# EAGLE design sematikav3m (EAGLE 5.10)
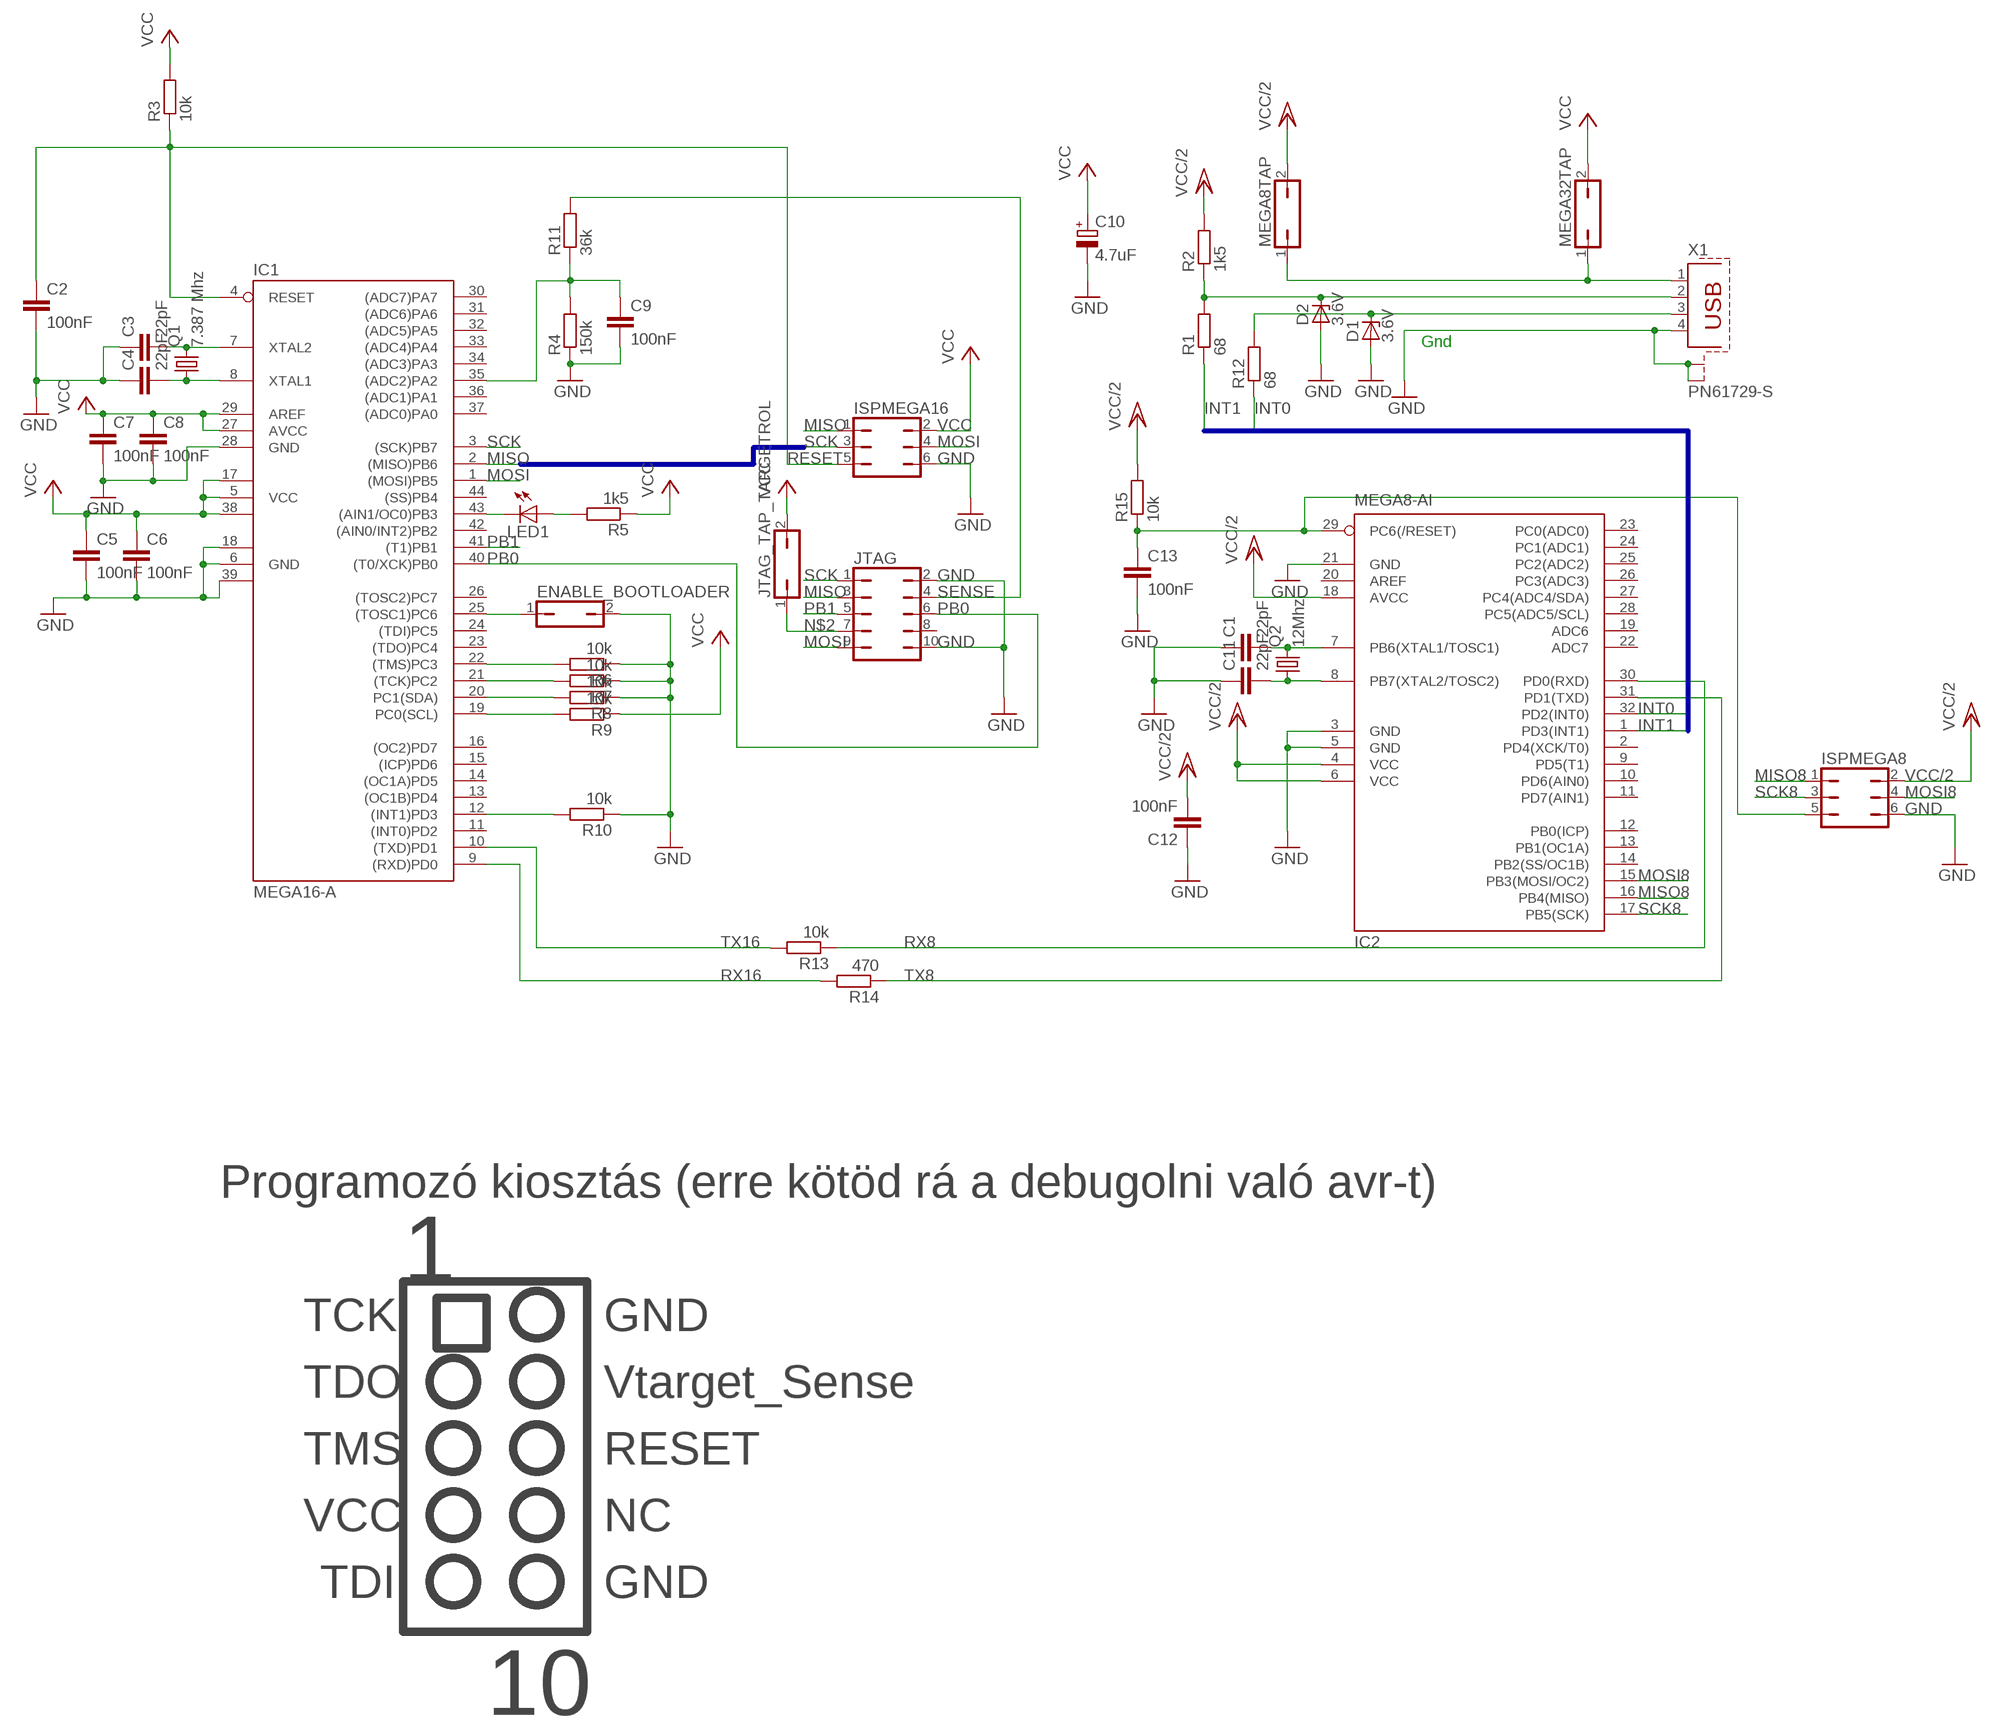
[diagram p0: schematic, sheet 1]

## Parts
C1  22pF  C-EUC1206  [C1206]
C2  100nF  C-EUC1206  [C1206]
C3  22pF  C-EUC1206  [C1206]
C4  22pF  C-EUC1206  [C1206]
C5  100nF  C-EUC1206  [C1206]
C6  100nF  C-EUC1206  [C1206]
C7  100nF  C-EUC1206  [C1206]
C8  100nF  C-EUC1206  [C1206]
C9  100nF  C-EUC1206  [C1206]
C10  4.7uF  CPOL-EUE2,5-6E  [E2,5-6E]
C11  22pF  C-EUC1206  [C1206]
C12  100nF  C-EUC1206  [C1206]
C13  100nF  C-EUC1206  [C1206]
D1  3.6V  ZENER-DIODEDO35Z10  [DO35Z10]
D2  3.6V  ZENER-DIODEDO35Z10  [DO35Z10]
ENABLE_BOOTLOADER  JP1Q  [JP1]
IC1  MEGA16-A  [TQFP44]
IC2  MEGA8-AI  [TQFP32-08]
ISPMEGA8  JP3Q  [JP3Q]
ISPMEGA16  JP3Q  [JP3Q]
JTAG  JP5Q  [JP5Q]
JTAG_TAP_TARGETROL  JP1Q  [JP1]
LED1  LED3MM  [LED3MM]
MEGA8TAP  JP1Q  [JP1]
MEGA32TAP  JP1Q  [JP1]
Q1  7.387 Mhz  CRYSTALHC49U-V  [HC49U-V]
Q2  12Mhz  CRYSTALHC49U-V  [HC49U-V]
R1  68  R-EU_R1206  [R1206]
R2  1k5  R-EU_R1206  [R1206]
R3  10k  R-EU_R1206  [R1206]
R4  150k  R-EU_R1206  [R1206]
R5  1k5  R-EU_R1206  [R1206]
R6  10k  R-EU_R1206  [R1206]
R7  10k  R-EU_R1206  [R1206]
R8  10k  R-EU_R1206  [R1206]
R9  10k  R-EU_R1206  [R1206]
R10  10k  R-EU_R1206  [R1206]
R11  36k  R-EU_R1206  [R1206]
R12  68  R-EU_R1206  [R1206]
R13  10k  R-EU_R1206  [R1206]
R14  470  R-EU_R1206  [R1206]
R15  10k  R-EU_R1206  [R1206]
X1  PN61729-S  [PN61729-S]

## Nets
D+: D1.C R12.2 X1.3
D-: D2.C R1.2 R2.1 X1.2
GND: C1.1 C2.2 C3.1 C4.1 C5.2 C6.2 C7.2 C8.2 C9.2 C10.- C11.1 C12.1 C13.2 D1.A D2.A ENABLE_BOOTLOADER.2 IC1.6(GND) IC1.18(GND1) IC1.28(GND) IC1.39(GND2) IC2.3(GND) IC2.5(GND) IC2.21(GND) ISPMEGA8.6 ISPMEGA16.6 JTAG.2 JTAG.10 R4.1 R6.1 R7.1 R8.1 R10.1 X1.4 X1.S1 X1.S2
INT0: IC2.32(PD2(INT0)) R12.1
INT1: IC2.1(PD3(INT1)) R1.1
MISO: IC1.2((MISO)PB6) ISPMEGA16.1 JTAG.3
MISO8: IC2.16(PB4(MISO)) ISPMEGA8.1
MOSI: IC1.1((MOSI)PB5) ISPMEGA16.4 JTAG.9
MOSI8: IC2.15(PB3(MOSI/OC2)) ISPMEGA8.4
N$2: JTAG.7 JTAG_TAP_TARGETROL.1
N$6: C11.2 IC2.8(PB7(XTAL2/TOSC2)) Q2.1
N$7: C1.2 IC2.7(PB6(XTAL1/TOSC1)) Q2.2
N$9: IC1.22((TMS)PC3) R6.2
N$10: C3.2 IC1.7(XTAL2) Q1.2
N$11: C4.2 IC1.8(XTAL1) Q1.1
N$12: C9.1 IC1.35((ADC2)PA2) R4.2 R11.1
N$13: IC1.21((TCK)PC2) R7.2
N$14: IC1.43((AIN1/OC0)PB3) LED1.K(C)
N$15: LED1.A R5.2
N$16: ENABLE_BOOTLOADER.1 IC1.25((TOSC1)PC6)
N$17: IC1.20(PC1(SDA)) R8.2
N$18: IC1.19(PC0(SCL)) R9.2
N$19: IC1.12((INT1)PD3) R10.2
N$23: MEGA8TAP.1 MEGA32TAP.1 X1.1
PB0: IC1.40((T0/XCK)PB0) JTAG.6
PB1: IC1.41((T1)PB1) JTAG.5
RESET: C2.1 IC1.4(RESET) ISPMEGA16.5 R3.1
RESET8: C13.1 IC2.29(PC6(/RESET)) ISPMEGA8.5 R15.1
RX8: IC2.30(PD0(RXD)) R13.1
RX16: IC1.9((RXD)PD0) R14.2
SCK: IC1.3((SCK)PB7) ISPMEGA16.3 JTAG.1
SCK8: IC2.17(PB5(SCK)) ISPMEGA8.3
SENSE: JTAG.4 R11.2
TX8: IC2.31(PD1(TXD)) R14.1
TX16: IC1.10((TXD)PD1) R13.2
VCC: C5.1 C6.1 C7.1 C8.1 C10.+ IC1.5(VCC) IC1.17(VCC1) IC1.27(AVCC) IC1.29(AREF) IC1.38(VCC2) ISPMEGA16.2 JTAG_TAP_TARGETROL.2 MEGA32TAP.2 R3.2 R5.1 R9.1
VCC/2: C12.2 IC2.4(VCC) IC2.6(VCC) IC2.18(AVCC) ISPMEGA8.2 MEGA8TAP.2 R2.2 R15.2
Unconnected: IC1.11((INT0)PD2) IC1.13((OC1B)PD4) IC1.14((OC1A)PD5) IC1.15((ICP)PD6) IC1.16((OC2)PD7) IC1.23((TDO)PC4) IC1.24((TDI)PC5) IC1.26((TOSC2)PC7) IC1.30((ADC7)PA7) IC1.31((ADC6)PA6) IC1.32((ADC5)PA5) IC1.33((ADC4)PA4) IC1.34((ADC3)PA3) IC1.36((ADC1)PA1) IC1.37((ADC0)PA0) IC1.42((AIN0/INT2)PB2) IC1.44((SS)PB4) IC2.2(PD4(XCK/T0)) IC2.9(PD5(T1)) IC2.10(PD6(AIN0)) IC2.11(PD7(AIN1)) IC2.12(PB0(ICP)) IC2.13(PB1(OC1A)) IC2.14(PB2(SS/OC1B)) IC2.19(ADC6) IC2.20(AREF) IC2.22(ADC7) IC2.23(PC0(ADC0)) IC2.24(PC1(ADC1)) IC2.25(PC2(ADC2)) IC2.26(PC3(ADC3)) IC2.27(PC4(ADC4/SDA)) IC2.28(PC5(ADC5/SCL)) JTAG.8

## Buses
B$1
B$2

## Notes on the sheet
- Gnd
- Programozó kiosztás (erre kötöd rá a debugolni való avr-t)
- 1
- TCK | GND
- TDO | Vtarget_Sense
- TMS | RESET
- VCC | NC
- TDI | GND
- 10

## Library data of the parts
C1-C9 C11-C13 = rcl:C-EU: CAPACITOR, European symbol
C10 = rcl:CPOL-EU: POLARIZED CAPACITOR, European symbol
D1 D2 = diode:ZENER-DIODE: Z-Diode
ENABLE_BOOTLOADER JTAG_TAP_TARGETROL MEGA8TAP MEGA32TAP = jumper:JP1Q: JUMPER
IC1 = atmel:MEGA16: MICROCONTROLLER 16 Kbytes FLASH 1 kbytes SRAM 512 bytes EEPROM USART 8-channel 10 bit ADC Source: avr.lbr
IC2 = atmel:MEGA8: MICROCONTROLLER 8 Kbytes FLASH, 1 kbytes SRAM, 512 bytes EEPROM, USART, 6-channel 10 bit ADC, 2-channel 8 bit ADC Pin compatible with Atmega48, ATMega88, ATMega168 Source: avr.lbr
ISPMEGA8 ISPMEGA16 = jumper:JP3Q: JUMPER
JTAG = jumper:JP5Q: JUMPER
LED1 = led:LED: LED
Q1 Q2 = crystal:CRYSTAL: CRYSTAL
R1-R15 = resistor:R-EU_: RESISTOR, European symbol
X1 = con-berg:PN61729-S: BERG USB connector

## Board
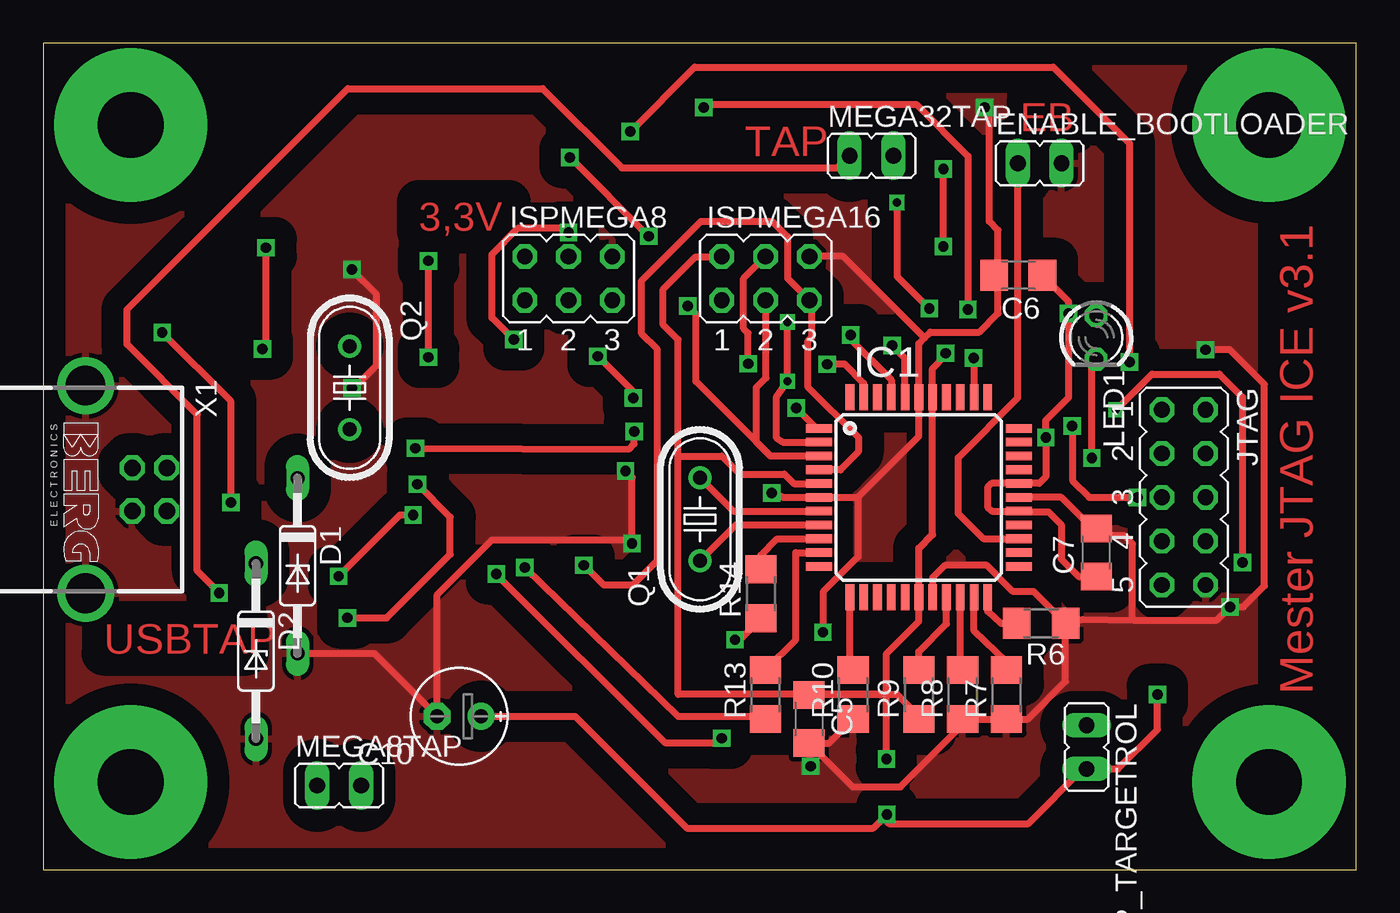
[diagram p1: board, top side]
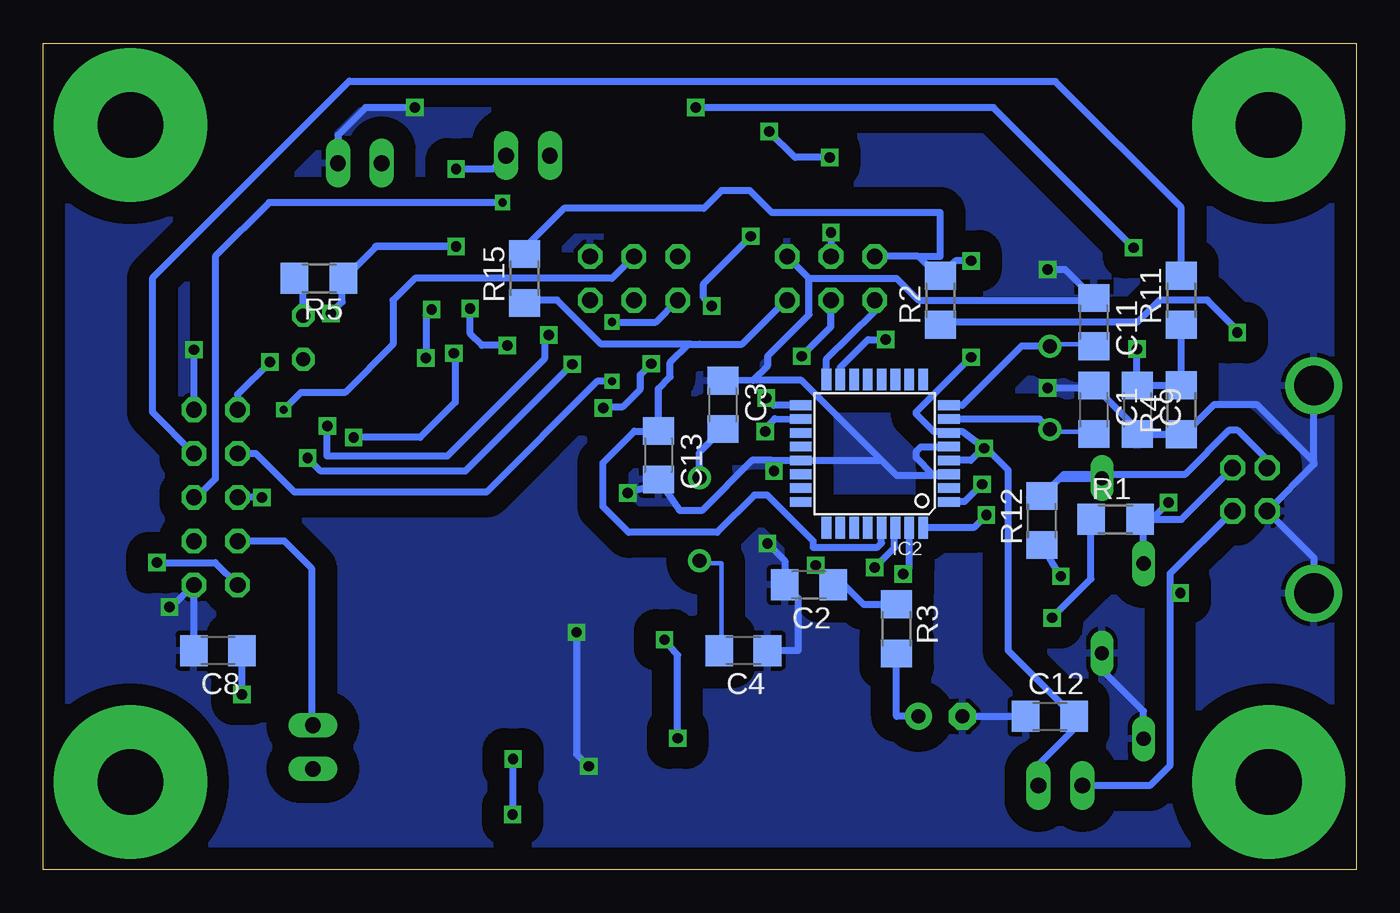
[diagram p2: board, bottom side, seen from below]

Size 76.18 x 47.93 mm. Coordinates in mm from the lower left corner, seen from the top.
Outline: 0,0 76.18,0 76.18,47.93 0,47.93 0,0
Copper layers (1*16): Top 0.035mm / dielectric 1.5mm / Bottom 0.035mm
Design rules "default *": minimum track width 10mil, minimum drill 19mil, track to track 8mil, track to pad 8mil, pad to pad 8mil, via to via 8mil, smd to smd 8mil, copper to edge 40mil, drill to drill 8mil, minimum pad ring 10mil, minimum via ring 8mil, stop-mask expansion 4mil, vias tented up to drill 0mil, thermal gap 10mil

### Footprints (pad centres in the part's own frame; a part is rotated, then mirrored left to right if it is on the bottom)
C1206 = smd 1.6 x 1.8: 1 -1.4,0; 2 1.4,0
E2,5-6E = drill 0.813 pad 1.575 round: + -1.27,0 | drill 0.813 pad 1.575 octagon: - 1.27,0
DO35Z10 = drill 0.813 long: A 5.08,0; C -5.08,0
JP1 = drill 0.914 long: 1 0,-1.27; 2 0,1.27
TQFP44 = smd 1.5 x 0.5: 1 -5.8,4; 2 -5.8,3.2; 3 -5.8,2.4; 4 -5.8,1.6; 5 -5.8,0.8; 6 -5.8,0; 7 -5.8,-0.8; 8 -5.8,-1.6; 9 -5.8,-2.4; 10 -5.8,-3.2; 11 -5.8,-4; 23 5.8,-4; 24 5.8,-3.2; 25 5.8,-2.4; 26 5.8,-1.6; 27 5.8,-0.8; 28 5.8,0; 29 5.8,0.8; 30 5.8,1.6; 31 5.8,2.4; 32 5.8,3.2; 33 5.8,4 | smd 0.5 x 1.5: 12 -4,-5.8; 13 -3.2,-5.8; 14 -2.4,-5.8; 15 -1.6,-5.8; 16 -0.8,-5.8; 17 0,-5.8; 18 0.8,-5.8; 19 1.6,-5.8; 20 2.4,-5.8; 21 3.2,-5.8; 22 4,-5.8; 34 4,5.8; 35 3.2,5.8; 36 2.4,5.8; 37 1.6,5.8; 38 0.8,5.8; 39 0,5.8; 40 -0.8,5.8; 41 -1.6,5.8; 42 -2.4,5.8; 43 -3.2,5.8; 44 -4,5.8
TQFP32-08 = smd 1.27 x 0.559: 1 -4.293,2.8; 2 -4.293,2; 3 -4.293,1.2; 4 -4.293,0.4; 5 -4.293,-0.4; 6 -4.293,-1.2; 7 -4.293,-2; 8 -4.293,-2.8; 17 4.293,-2.8; 18 4.293,-2; 19 4.293,-1.2; 20 4.293,-0.4; 21 4.293,0.4; 22 4.293,1.2; 23 4.293,2; 24 4.293,2.8 | smd 0.559 x 1.27: 9 -2.8,-4.293; 10 -2,-4.293; 11 -1.2,-4.293; 12 -0.4,-4.293; 13 0.4,-4.293; 14 1.2,-4.293; 15 2,-4.293; 16 2.8,-4.293; 25 2.8,4.293; 26 2,4.293; 27 1.2,4.293; 28 0.4,4.293; 29 -0.4,4.293; 30 -1.2,4.293; 31 -2,4.293; 32 -2.8,4.293
JP3Q = drill 0.914 octagon: 1 -2.54,-1.27; 2 -2.54,1.27; 3 0,-1.27; 4 0,1.27; 5 2.54,-1.27; 6 2.54,1.27
JP5Q = drill 0.914 octagon: 1 -5.08,-1.27; 2 -5.08,1.27; 3 -2.54,-1.27; 4 -2.54,1.27; 5 0,-1.27; 6 0,1.27; 7 2.54,-1.27; 8 2.54,1.27; 9 5.08,-1.27; 10 5.08,1.27
LED3MM = drill 0.813 octagon: A -1.27,0; K 1.27,0
HC49U-V = drill 0.813 round: 1 -2.413,0; 2 2.413,0
R1206 = smd 1.6 x 1.803: 1 -1.422,0; 2 1.422,0
PN61729-S = drill 0.95 octagon: 1 1.25,4.71; 2 -1.25,4.71; 3 -1.25,2.71; 4 1.25,2.71 | drill 2.3 pad 2.9 round: S1 -6.02,0; S2 6.02,0

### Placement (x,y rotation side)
C1  15.24,26.67 270 bottom
C2  31.75,16.51 180 bottom
C3  36.75,26.95 270 bottom
C4  35.56,12.7 180 bottom
C5  44.42,8.74 270 top
C6  56.57,34.47 180 top
C7  61.09,18.39 90 top
C8  66.04,12.7 180 bottom
C9  12.7,26.67 270 bottom
C10  24.13,8.89 180 top
C11  15.24,31.75 270 bottom
C12  17.78,8.89 0 bottom
C13  40.49,24.03 270 bottom
D1  14.76,17.63 270 top
D2  12.34,12.67 270 top
ENABLE_BOOTLOADER  57.81,40.97 270 top
IC1  50.8,21.59 0 top
IC2  27.94,24.13 180 bottom
ISPMEGA8  30.48,34.29 0 top
ISPMEGA16  41.91,34.29 0 top
JTAG  66.17,21.59 270 top
JTAG_TAP_TARGETROL  60.53,7.11 180 top
LED1  61.09,30.86 270 top
MEGA8TAP  17.17,4.88 270 top
MEGA32TAP  48.06,41.4 270 top
Q1  38.1,20.32 90 top
Q2  17.78,27.94 270 top
R1  13.97,20.32 0 bottom
R2  24.13,33.02 90 bottom
R3  26.67,13.97 270 bottom
R4  10.16,26.67 90 bottom
R5  60.17,34.29 180 bottom
R6  57.89,14.29 180 top
R7  55.88,10.16 90 top
R8  53.34,10.16 90 top
R9  50.8,10.16 90 top
R10  46.99,10.16 90 top
R11  10.16,33.02 90 bottom
R12  18.24,20.24 90 bottom
R13  41.91,10.16 90 top
R14  41.63,16 90 top
R15  48.26,34.29 90 bottom
X1  2.46,22.05 270 top

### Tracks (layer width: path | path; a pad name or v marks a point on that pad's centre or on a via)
D+
  Bottom 0.254: R12.2 19.05,21.59
  Bottom 0.406: X1.3 5.17,23.77 6.88,25.48 7.39,25.48 9.96,22.91 16.99,22.91 R12.2 17.2,22.71 D1.C
D-  (via drill 0.6)
  Top 0.406: v6.91,31.14 10.9,27.15 v10.9,21.29
  Bottom 0.254: R1.2 12.7,20.32 | 24.13,31.75 R2.1
  Bottom 0.406: 24.13,31.75 12.7,31.75 11.43,33.02 8.64,33.02 6.91,31.29 v6.91,31.14 | 11.86,20.32 10.15,20.32 X1.2 | 11.86,20.32 v10.9,21.29 | 11.86,20.32 R1.2 12.34,20.12 D2.C
GND  (via drill 0.6)
  Top 0.406: v17.91,27.94 18.03,27.94 19.3,29.21 19.3,33.4 v17.91,34.8 | R6.1 60.32,14.52 63.24,14.48 | R6.1 59.31,10.92 57.12,8.74 R7.1 R8.1 53.34,8.41 49.73,4.8 46.96,4.8 44.78,6.98 | R6.1 | IC1.18 51.6,16.93 52.32,17.65 54.74,17.65 56.26,16.13 57.47,16.13 R6.1 | v33.78,23.11 34.16,22.73 v34.16,18.92 33.96,19.13 26.04,19.13 22.86,15.95 C10.- 19.2,12.55 D1.A | v42.27,21.84 42.95,21.59 IC1.6 47.27,21.59 | 47.27,21.59 50.8,25.12 IC1.39 50.8,30.5 51.13,30.84 | v67.44,30.15 68.83,30.15 70.84,28.14 70.84,16.46 69.62,15.24 v68.85,15.24 68.09,14.48 63.24,14.48 | 55.4,33.78 55.4,32.26 54.3,31.17 51.46,31.17 51.13,30.84 | 55.4,33.78 55.4,37.08 54.89,37.59 54.89,43.92 v54.61,44.2 | ISPMEGA16.6 46.41,35.56 51.13,30.84 | 60.85,19.79 C7.2 | 60.85,19.79 59.05,21.59 IC1.28 | 60.85,19.79 61.29,19.36 62.74,19.36 63.2,18.9 63.2,14.52 63.24,14.48 | 44.78,6.98 C5.2 45.59,7.34 R10.1 | C6.2 55.17,34.01 55.4,33.78 | 47.27,21.59 47.27,18.14 45.24,16.1 v45.24,13.77 | v44.53,5.99 44.53,6.73 44.78,6.98
  Bottom 0.254: 15.24,33.02 C11.1 | R4.1 10.16,25.4 | 24.13,22.86 IC2.3 | 15.24,27.94 C1.1
  Bottom 0.406: 15.24,33.02 25.4,33.02 26.67,34.29 31.75,34.29 | 31.75,34.29 ISPMEGA8.6 | 24.13,22.86 26.67,22.86 27.54,23.73 | C10.- C12.1 | IC2.3 24.58,22.93 25.53,23.88 25.53,24.26 25.27,24.51 23.67,24.51 IC2.5 | v17.91,27.94 15.24,27.94 | v17.91,34.8 16.89,34.8 C11.1 | C4.1 32.38,12.7 32.38,15.75 C2.2 33.15,17.91 v34.16,18.92 | 27.54,23.73 IC2.21 33.91,23.73 | C8.2 67.44,16.38 JTAG.10 68.71,15.24 v68.85,15.24 | 33.91,23.73 35.07,23.73 37.97,20.83 39.25,20.83 C13.2 40.89,22.23 v42.27,21.84 | v33.78,23.11 33.78,23.6 33.91,23.73 | 31.75,34.29 31.75,32.18 34.14,29.79 34.14,29.23 35,28.37 | 35,28.37 C3.1 | 27.54,23.73 32.18,28.37 35,28.37 | C1.1 12.7,25.53 C9.2 12.68,25.25 R4.1 9.98,25.25 8.25,26.98 5.79,26.98 2.46,23.65 | v67.44,30.15 JTAG.2 | v54.61,44.2 57.48,44.2 59.08,42.6 ENABLE_BOOTLOADER.2 | 2.46,23.65 2.46,23.51 X1.4 2.46,18.09 X1.S2 | 2.46,23.65 X1.S1 | v45.24,13.77 45.24,6.71 v44.53,5.99 | D1.A 14.76,11.61 12.34,9.2 D2.A
  pour Bottom (isolate 1.27): 0,0 76.2,0 76.2,48.26 0,48.26
  pour Top (isolate 1.27): 0,0 76.2,0 76.2,48.26 0,48.26
INT0  (via drill 0.6)
  Top 0.406: v21.46,20.57 20.7,20.57 v17.14,17.02
  Bottom 0.406: v21.46,20.57 22.2,19.84 IC2.32 | v17.14,17.02 17.17,17.02 R12.1
INT1  (via drill 0.6)
  Top 0.406: v17.65,14.61 19.94,14.61 23.62,18.29 23.62,20.45 v21.72,22.35
  Bottom 0.406: R1.1 15.39,16.87 v17.65,14.61 | v21.72,22.35 22.73,21.34 IC2.1
MISO  (via drill 0.48)
  Top 0.406: v43.18,31.75 v43.18,28.32 42.55,27.43 42.55,25.02 42.9,24.79 IC1.2
  Bottom 0.406: ISPMEGA16.1 40.64,31.75 v43.18,31.75 | v43.18,28.32 44.04,28.32 50.47,21.89 61.59,21.89 63.83,24.13 JTAG.3
MISO8
  Bottom 0.406: IC2.16 30.74,29.64 27.95,32.36 ISPMEGA8.1
MOSI  (via drill 0.48, 0.6)
  Top 0.406: v40.89,29.34 40.89,31.11 40.64,31.37 40.64,34.29 ISPMEGA16.4 | v62.23,26.67 62.26,26.67 64.33,28.74 68.24,28.74 69.57,27.41 v69.57,17.8 | 43.92,26.67 v43.69,26.77 44.87,25.59 IC1.1
  Bottom 0.406: ISPMEGA16.4 43.18,34.29 54.61,34.29 55.88,33.02 55.88,30.46 58.67,27.66 61.24,27.66 v62.23,26.67 | v40.89,29.34 41.53,28.7 41.53,27.86 42.55,26.85 43.59,26.85 v43.69,26.77 | v69.57,17.8 66.19,17.8 JTAG.9
MOSI8  (via drill 0.6)
  Top 0.406: v27.3,30.73 26.04,32 26.04,35.69 27.56,37.21 30.23,37.21 v30.48,36.96
  Bottom 0.406: v27.3,30.73 28.32,30.73 29.95,29.11 29.94,29.1 IC2.15 | v30.48,36.96 ISPMEGA8.4
N$2
  Bottom 0.406: JTAG.7 62.18,19.05 60.58,17.45 60.58,8.43 JTAG_TAP_TARGETROL.1
N$6
  Bottom 0.254: C11.2 15.24,30.48 17.78,30.48 Q2.1
  Bottom 0.406: Q2.1 19.43,30.35 22.86,26.92 IC2.8
N$7
  Bottom 0.254: C1.2 15.24,25.4 17.78,25.4 Q2.2
  Bottom 0.406: IC2.7 18.38,26.13 Q2.2
N$9
  Top 0.406: R6.2 55.56,14.29 54.8,14.99 54.8,15.73 IC1.22
N$10
  Top 0.406: IC1.7 40.04,20.79 Q1.2
  Bottom 0.406: Q1.2 38.1,24.2 C3.2
N$11
  Top 0.406: IC1.8 40.18,19.99 Q1.1
  Bottom 0.254: C4.2 36.83,12.7 36.83,17.78 38.1,17.78 Q1.1
N$12  (via drill 0.6)
  Top 0.406: IC1.35 54,29.13 v53.98,29.67 | v53.64,32.49 53.64,41.38 50.65,44.37 38.51,44.37 v38.33,44.2 | v12.93,36.07 12.93,30.4 v12.73,30.2
  Bottom 0.254: R11.1 10.16,31.75
  Bottom 0.406: R11.1 R4.2 10.16,28.07 C9.1 12.73,28.09 v12.73,30.2 | v53.98,29.67 53.98,32.16 v53.64,32.49 | v38.33,44.2 21.06,44.2 v12.93,36.07
N$13
  Top 0.406: R7.2 55.88,12.07 54,13.84 54,15.69 IC1.21
N$14  (via drill 0.6)
  Top 0.406: v60.83,23.88 60.83,29.34 LED1.K | v45.49,29.31 46.51,29.31 47.6,28.22 IC1.43 | IC1.43
  Bottom 0.406: v60.83,23.88 60.07,23.11 51.69,23.11 v45.49,29.31
N$15
  Bottom 0.406: R5.2 61.09,33.78 LED1.A
N$16
  Top 0.406: IC1.25 56.59,19.2 54.53,19.2 53.09,20.65 53.09,23.9 56.54,27.36 ENABLE_BOOTLOADER.1
N$17
  Top 0.254: 53.2,15.21 IC1.20 | R8.2 53.34,11.43
  Top 0.406: 53.2,15.21 53.2,11.72 R8.2
N$18
  Top 0.406: IC1.19 52.4,14.25 50.8,12.65 R9.2
N$19
  Top 0.406: IC1.12 46.8,11.77 R10.2
N$23  (via drill 0.6)
  Top 0.406: MEGA32TAP.1 46.08,40.69 33.58,40.69 28.98,45.29 17.68,45.29 4.88,32.49 4.88,30.46 8.94,26.39 8.94,17.32 v10.21,16.05
  Bottom 0.406: MEGA8TAP.1 11.99,4.88 10.8,6.07 10.8,15.95 | 10.8,15.95 10.8,17.18 X1.1 | v10.21,16.05 10.69,16.05 10.8,15.95
N$29  (via drill 3.81 pad 8.89)
  other vias: 71.12,43.18
N$30  (via drill 3.81 pad 8.89)
  other vias: 71.12,5.08
N$31  (via drill 3.81 pad 8.89)
  other vias: 5.08,43.18
N$32  (via drill 3.81 pad 8.89)
  other vias: 5.08,5.08
PB0  (via drill 0.48, 0.6)
  Top 0.406: v49.53,38.68 49.55,38.66 49.55,34.39 v51.41,32.54 | IC1.40 50,29.65 v49.25,30.4
  Bottom 0.406: v49.53,38.68 63.07,38.68 66.19,35.56 66.19,22.66 67.26,21.59 JTAG.6 | v51.41,32.54 51.41,31.09 50.72,30.4 v49.25,30.4
PB1  (via drill 0.6)
  Top 0.406: v63.49,21.59 60.68,21.59 59.71,22.55 59.71,25.71 v59.69,25.73 | v46.84,31.01 46.84,30.76 49.2,28.4 IC1.41 | IC1.41
  Bottom 0.406: v59.69,25.73 59.69,24.02 59.73,23.99 52.75,23.99 47.07,29.67 47.07,30.79 v46.84,31.01 | v63.49,21.59 JTAG.5
RESET  (via drill 0.6)
  Top 0.406: v31.37,17.65 32.51,16.51 34.21,16.51 35.64,17.93 35.64,30.18 34.72,31.09 34.72,34.16 38.15,37.59 42.29,37.59 43.18,36.7 43.18,34.29 ISPMEGA16.5 44.58,32.89 44.58,30.86 44.35,30.63 44.35,28.02 47.27,25.09 47.3,25.09 47.3,24.23 46.25,23.19 IC1.4 | IC1.4
  Bottom 0.406: v31.37,17.65 30.61,16.77 C2.1 29.72,16.51 28.57,15.37 26.7,15.37 R3.1
RESET8
  Bottom 0.254: R15.1 48.26,33.02
  Bottom 0.406: IC2.29 27.54,18.94 27.81,18.67 31.5,18.67 31.5,19.05 34.16,21.72 34.92,21.72 37.08,19.56 42.21,19.56 43.71,21.06 43.71,23.6 41.88,25.43 C13.1 40.49,27.89 39.8,28.57 39.8,29.41 38.73,30.48 | 38.73,30.48 43.81,30.48 46.35,33.02 48.11,33.02 R15.1 | 38.73,30.48 38.61,30.48 | 38.61,30.48 38.1,30.48 | ISPMEGA8.5 33.1,33.02 35.64,30.48 38.61,30.48
RX8  (via drill 0.61)
  Top 0.254: 41.91,8.89 R13.1
  Top 0.406: v27.94,17.53 36.83,8.89 41.91,8.89
  Bottom 0.254: IC2.30 26.67,20.32
  Bottom 0.406: v27.94,17.53 26.8,18.67 26.8,19.78 IC2.30
RX16
  Top 0.406: IC1.9 42.58,19.19 41.63,18.24 R14.2
SCK  (via drill 0.6)
  Top 0.406: ISPMEGA16.3 41.94,32.99 41.94,28.52 41.38,27.96 41.38,24.79 42.18,23.99 42.2,23.99 | 42.2,23.99 37.87,28.32 37.87,32.21 v37.39,32.69 | v35.13,36.73 v30.56,41.3 | v34.06,42.8 37.8,46.53 58.6,46.53 63.02,42.11 v63.02,29.44 | 42.2,23.99 IC1.3
  Bottom 0.406: v35.13,36.73 37.87,33.98 37.87,33.17 v37.39,32.69 | v30.56,41.3 32.56,41.3 v34.06,42.8 | v63.02,29.44 64.9,27.56 JTAG.1
SCK8  (via drill 0.6)
  Top 0.406: v32.18,29.77 34.24,27.71 v34.24,27.36
  Bottom 0.406: v32.18,29.77 30.48,31.47 ISPMEGA8.3 | v34.24,27.36 33.81,26.93 IC2.17
SENSE
  Bottom 0.254: R11.2 10.16,34.29
  Bottom 0.406: 58.45,45.7 58.42,45.72 | 58.45,45.7 69.85,34.29 69.85,26.54 JTAG.4 | R11.2 10.16,38.4 17.45,45.7 58.45,45.7
TX8  (via drill 0.6)
  Top 0.406: v26.29,17.14 36.07,7.37 39.12,7.37 v39.37,7.62 | v40.13,13.34 40.41,13.34 R14.1
  Bottom 0.406: IC2.31 25.94,17.49 v26.29,17.14 | v39.37,7.62 39.37,12.45 v40.13,13.34
TX16
  Top 0.406: IC1.10 43.66,18.39 43.66,13.34 R13.2
VCC  (via drill 0.6)
  Top 0.254: 50.8,8.89 R9.1
  Top 0.406: 50.8,8.89 49.53,10.16 48.92,10.16 | 48.92,10.16 48.56,10.16 | 48.56,10.16 36.83,10.16 36.83,23.98 | C10.+ 30.86,8.89 37.34,2.41 48.16,2.41 v48.95,3.2 48.95,2.79 49.07,2.67 57.15,2.67 60.32,5.84 JTAG_TAP_TARGETROL.2 62.36,5.84 64.64,8.13 v64.64,10.16 | 48.92,10.16 48.92,12.52 50.8,14.4 IC1.17 50.8,18.62 | IC1.5 43.55,22.39 43,22.94 40.41,22.94 39.37,23.98 36.83,23.98 | 51.6,19.44 51.6,27.29 IC1.38 51.59,27.4 51.59,29.06 52.35,29.82 v52.35,29.95 | 51.6,19.44 50.8,18.64 50.8,18.62 | 51.6,19.44 51.6,19.42 50.8,18.62 | v48.92,6.43 48.92,10.16 | v52.22,36.14 v52.22,40.64 | 36.83,23.98 36.83,30.73 35.97,31.6 35.97,33.65 37.85,35.53 39.34,35.53 ISPMEGA16.2 | C7.1 60.07,16.99 59.05,18.01 59.05,20.02 58.32,20.75 56.64,20.75 IC1.27 55.03,20.79 54.79,21.03 54.79,22.17 55.02,22.4 56.59,22.4 IC1.29 56.61,22.4 57.78,22.4 58.17,22.78 v58.17,25.07 58.17,26.06 59.49,27.38 v59.49,32.26 59.49,32.95 C6.1 | C5.1 48.54,10.14 48.56,10.16
  Bottom 0.254: R3.2 26.67,12.7 | C8.1 64.77,12.7
  Bottom 0.406: R3.2 26.67,8.89 C10.+ | v64.64,10.16 C8.1 | v48.92,6.43 48.92,3.58 v48.95,3.2 | 56.9,36.14 v52.22,36.14 56.84,36.14 58.83,34.16 | v58.17,25.07 54.3,25.07 52.27,27.1 52.27,29.87 v52.35,29.95 | 58.83,34.16 58.83,32.92 v59.49,32.26 | v52.22,40.64 50.09,40.64 MEGA32TAP.2 | 58.83,34.16 58.83,34.21 R5.1
VCC/2  (via drill 0.6)
  Top 0.406: v22.35,29.72 v22.35,35.31 | v21.59,24.43 33.98,24.38 34.29,24.69 v34.29,25.4
  Bottom 0.254: 21.78,24.32 v21.59,24.43 | 24.13,25.4 IC2.6 | C12.2 16.51,8.89 | R15.2 48.26,35.56 | R2.2 24.13,34.29
  Bottom 0.406: 24.13,34.29 25.4,35.56 | 25.4,35.56 ISPMEGA8.2 | 25.4,35.56 24.13,35.56 24.13,38.1 33.91,38.1 35.18,39.37 36.83,39.37 37.85,38.35 45.97,38.35 48.26,36.07 R15.2 | IC2.4 22.37,23.73 21.78,24.32 21.35,24.32 20.19,23.16 20.19,12.7 C12.2 16.51,8.76 16.51,8.03 18.44,6.1 MEGA8TAP.2 | v21.59,24.43 22.86,25.4 24.13,25.4 24.51,25.4 25.53,26.42 25.53,26.54 v22.35,29.72 | v22.35,35.31 23.27,35.31 R2.2 | IC2.18 33.74,26.16 34.29,25.6 v34.29,25.4

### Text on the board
Top: EB | TAP | 3,3V | USBTAP | Mester JTAG ICE v3.1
